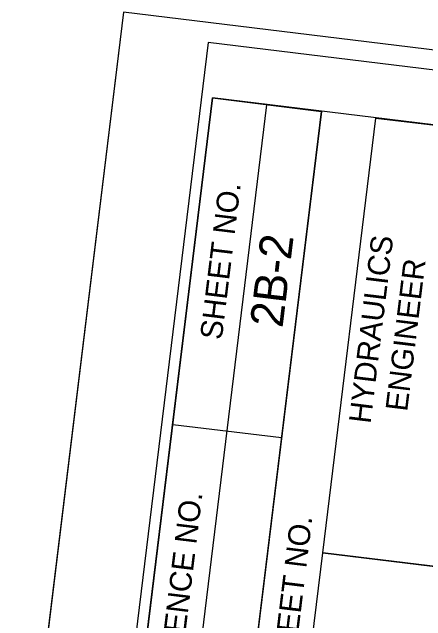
# Model space of a CAD drawing. Extents: x 480344 to 482186, y 489602 to 491961.
# Drawn here: x 480981.9 to 481076.3, y 491821.7 to 491960.6 of the extents above; entities that cross this region are included whole.
import ezdxf

# ---------------------------------------------------------------- set-up
doc = ezdxf.new("R2010")
doc.units = 0
for name, color, linetype in [('Sheet Cutting Line CELL', 7, 'Continuous'), ('Sheet Data Field CELL', 7, 'Continuous'), ('Sheet Plan CELL', 7, 'Continuous'), ('Sheet Plot Border Inside CELL', 7, 'Continuous'), ('Sheet Plot Border Outside CELL', 7, 'Continuous')]:
    doc.layers.add(name, color=color, linetype=linetype)

msp = doc.modelspace()

# ---------------------------------------------------------------- linework, layer by layer
at = {"layer": 'Sheet Cutting Line CELL'}
msp.add_line((481007.36, 491960.62), (480803.26, 490289.54), dxfattribs=at)
at = {"layer": 'Sheet Plan CELL'}
for p, q in [((481015.82, 491740.91), (481040.08, 491939.49)), ((481028.26, 491739.41), (481052.49, 491937.97)), ((481028.26, 491739.41), (481052.49, 491937.97)), ((481052.79, 491837.2), (481064.9, 491936.46)), ((481064.9, 491936.46), (481176.58, 491922.83)), ((481018.59, 491866.53), (481043.41, 491863.55)), ((481052.79, 491837.2), (481164.42, 491823.58)), ((481164.47, 491823.56), (481052.79, 491837.2))]:
    msp.add_line(p, q, dxfattribs=at)
for points in [[(481027.63, 491941.04), (480845.77, 490452.07), (481888.02, 490324.77), (482069.88, 491813.72)], [(481003.36, 491742.45), (481027.63, 491941.04), (481052.49, 491937.97), (481028.26, 491739.41)], [(481040.66, 491737.89), (481052.79, 491837.2), (481164.47, 491823.56), (481152.32, 491724.27)]]:
    msp.add_lwpolyline(points, close=True, dxfattribs=at)
at = {"layer": 'Sheet Plot Border Inside CELL'}
msp.add_lwpolyline([(481871.91, 490172.11), (482073.88, 491825.81), (481026.67, 491953.73), (480824.69, 490300.02)], close=True, dxfattribs=at)
at = {"layer": 'Sheet Plot Border Outside CELL'}
msp.add_lwpolyline([(481890.19, 490156.78), (482094.29, 491827.87), (481007.36, 491960.62), (480803.26, 490289.54)], close=True, dxfattribs=at)

# ---------------------------------------------------------------- texts
at = {"layer": 'Sheet Data Field CELL'}
msp.add_text('2B-2', height=7.5, rotation=83.0365, dxfattribs=at).set_placement((481043.61, 491888.41))
at = {"layer": 'Sheet Plan CELL'}
for s, height, p in [('SHEET NO.', 5, (481029.75, 491885.67)), ('HYDRAULICS', 5, (481063.7, 491866.56)), ('ENGINEER', 5, (481072.06, 491869.33)), ('PROJECT REFERENCE NO.', 5.0001, (481014.71, 491763.43)), ('R/W SHEET NO.', 5.0001, (481044.29, 491794.87))]:
    msp.add_text(s, height=height, rotation=83.0365, dxfattribs=at).set_placement(p)

doc.saveas('drawing.dxf')
